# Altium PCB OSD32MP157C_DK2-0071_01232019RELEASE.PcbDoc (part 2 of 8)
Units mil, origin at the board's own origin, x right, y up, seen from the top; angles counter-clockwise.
Board outline 3976.38 x 2795.28 mil, 6 copper layers (Top Layer, Signal Layer 1, Signal Layer 2, Signal Layer 3, Signal Layer 4, Bottom Layer), stack 61.268 mil thick; 404 components, 418 nets, 1720 pads, 1233 vias.
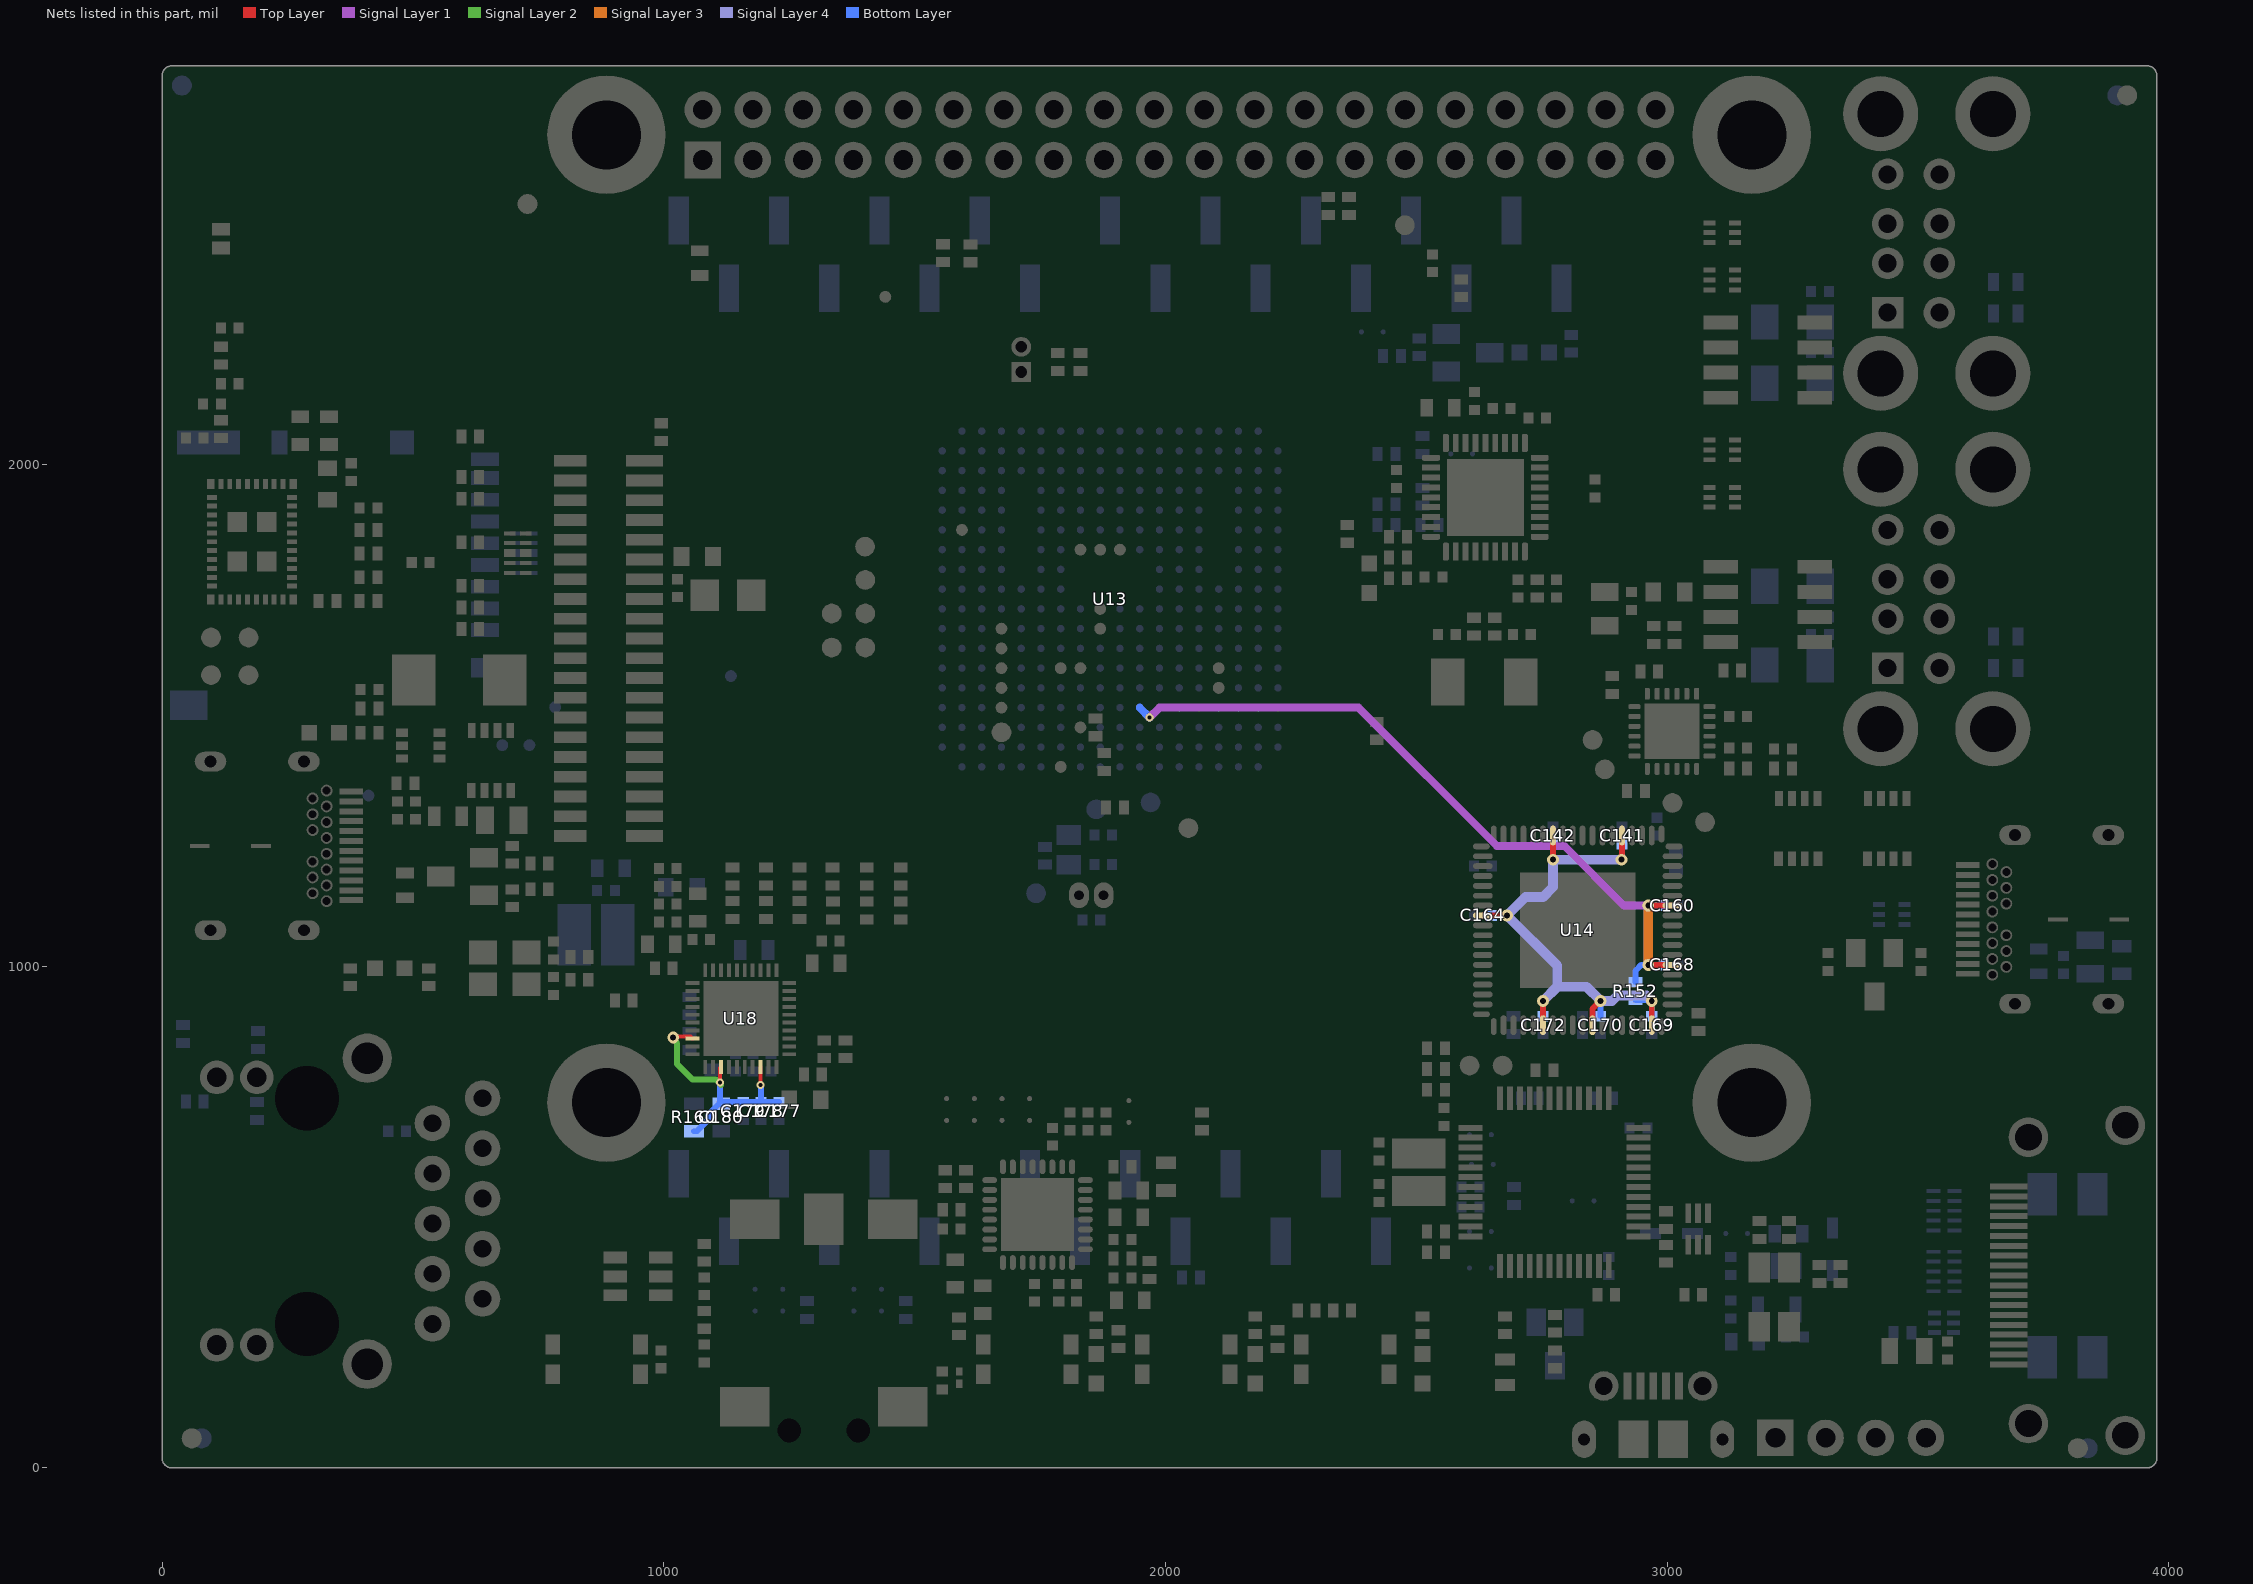
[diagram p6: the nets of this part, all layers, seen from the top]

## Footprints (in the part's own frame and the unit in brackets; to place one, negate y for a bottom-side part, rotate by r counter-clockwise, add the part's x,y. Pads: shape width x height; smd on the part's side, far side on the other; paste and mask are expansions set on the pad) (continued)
CON_HDMI_FCI-AMPHENOL_10029449-001RLF [mm]
  rect 0.3x1.9 smd mask+0.05: 1(4.75,8.5) 2(4.25,8.5) 3(3.75,8.5) 4(3.25,8.5) 5(2.75,8.5) 6(2.25,8.5) 7(1.75,8.5) 8(1.25,8.5) 9(0.75,8.5) 10(0.25,8.5) 11(-0.25,8.5) 12(-0.75,8.5) 13(-1.25,8.5) 14(-1.75,8.5) 15(-2.25,8.5) 16(-2.75,8.5) 17(-3.25,8.5) 18(-3.75,8.5) 19(-4.25,8.5)
  round 2 hole 1.35 mask+0.1: 20(7.25,7.5) 21(-7.25,7.5) 22(7.85,2.6) 23(-7.85,2.6)
  silkscreen extent -7.5,-1 7.5,8, body extent -8.1,-1 8.1,8.9, height 6.3
CON_JACK-3P5-SMT_LUMBERG_1503-13-VP3 [mm]
  rect 2.6x2 smd mask+0.05: 1(15.2,0)
  rect 2x2.5 smd mask+0.05: 2(15.2,3.5) 3(15.2,-3.5) 4(5.7,-4) 4(5.7,4)
  round 0.5 hole 1.2 unplated mask+0.1: NPTH1(4.5,-1.75) NPTH2(4.5,1.75)
  silkscreen extent 0,-3.55 14.6,3.55, body extent 0,-4.55 15.8,4.55, height 6.1
CON_MOLEX_53047-0210 [mm]
  oval 1x1.3 hole 0.5 mask+0.05: 1(-0.625,0) 2(0.625,0)
  silkscreen extent -2.12,-1.15 2.13,2.05, body extent -2.13,-1.15 2.13,2.05, height 4.2
CON_SAMTEC_SSW-106-22-X-S-VS [mil]
  rect 40x95 smd mask+1.97: 1(250,67.5) 2(150,-67.5) 3(50,67.5) 4(-50,-67.5) 5(-150,67.5) 6(-250,-67.5)
  silkscreen extent -310,-48 310,48, body extent -310,-101 310,102, height 385
CON_SAMTEC_SSW-108-22-X-S-VS [mil]
  rect 40x95 smd mask+1.97: 1(350,67.5) 2(250,-67.5) 3(150,67.5) 4(50,-67.5) 5(-50,67.5) 6(-150,-67.5) 7(-250,67.48) 8(-350,-67.48)
  silkscreen extent -410,-48 410,48, body extent -410,-101 410,102, height 385
CON_SAMTEC_SSW-110-22-X-S-VS [mil]
  rect 40x95 smd mask+1.97: 1(450,67.5) 2(350,-67.5) 3(250,67.5) 4(150,-67.5) 5(50,67.5) 6(-50,-67.5) 7(-150,67.48) 8(-250,-67.48) 9(-350,67.48) 10(-450,-67.48)
  silkscreen extent -510,-48 510,48, body extent -510,-101 510,102, height 385
CON_SAMTEC_TSW-104-07-G-S [mm]
  rect 1.85x1.85 / inner round 1.85 / far side rect 1.85x1.85 hole 1 mask+0.05: 1(-3.81,0)
  round 1.85 hole 1 mask+0.05: 2(-1.27,0) 3(1.27,0) 4(3.81,0)
  silkscreen extent -5.12,-1.3 5.12,1.3, body extent -5.21,-1.37 5.18,1.37, height 8.38
CON_SAMTEC_TSW-120-07-G-D [mm]
  rect 1.85x1.85 / inner round 1.85 / far side rect 1.85x1.85 hole 1 mask+0.05: 1(-24.13,-1.27)
  round 1.85 hole 1 mask+0.05: 2(-24.13,1.27) 3(-21.59,-1.27) 4(-21.59,1.27) 5(-19.05,-1.27) 6(-19.05,1.27) 7(-16.51,-1.27) 8(-16.51,1.27) 9(-13.97,-1.27) 10(-13.97,1.27) 11(-11.43,-1.27) 12(-11.43,1.27) 13(-8.89,-1.27) 14(-8.89,1.27) 15(-6.35,-1.27) 16(-6.35,1.27) 17(-3.81,-1.27) 18(-3.81,1.27) 19(-1.27,-1.27) 20(-1.27,1.27) 21(1.27,-1.27) 22(1.27,1.27) 23(3.81,-1.27) 24(3.81,1.27) 25(6.35,-1.27) 26(6.35,1.27) 27(8.89,-1.27) 28(8.89,1.27) 29(11.43,-1.27) 30(11.43,1.27) 31(13.97,-1.27) 32(13.97,1.27) 33(16.51,-1.27) 34(16.51,1.27) 35(19.05,-1.27) 36(19.05,1.27) 37(21.59,-1.27) 38(21.59,1.27) 39(24.13,-1.27) 40(24.13,1.27)
  silkscreen extent -25.4,-2.54 25.4,2.54, body extent -25.4,-2.55 25.4,2.54, height 8.38
CON_TE-CONNECTIVITY_2-1734248-0 [mm]
  rect 0.6x1.85 smd mask+0.05: 1(9.5,1.925) 3(8.5,1.925) 5(7.5,1.925) 7(6.5,1.925) 9(5.5,1.925) 11(4.5,1.925) 13(3.5,1.925) 15(2.5,1.925) 17(1.5,1.925) 19(0.5,1.925) 21(-0.5,1.925) 23(-1.5,1.925) 25(-2.5,1.925) 27(-3.5,1.925) 29(-4.5,1.925) 31(-5.5,1.925) 33(-6.5,1.925) 35(-7.5,1.925) 37(-8.5,1.925) 39(-9.5,1.925)
  rect 0.6x1.65 smd mask+0.05: 2(9.5,-1.825) 4(8.5,-1.825) 6(7.5,-1.825) 8(6.5,-1.825) 10(5.5,-1.825) 12(4.5,-1.825) 14(3.5,-1.825) 16(2.5,-1.825) 18(1.5,-1.825) 20(0.5,-1.825) 22(-0.5,-1.825) 24(-1.5,-1.825) 26(-2.5,-1.825) 28(-3.5,-1.825) 30(-4.5,-1.825) 32(-5.5,-1.825) 34(-6.5,-1.825) 36(-7.5,-1.825) 38(-8.5,-1.825) 40(-9.5,-1.825)
  silkscreen extent -13.7,-2.8 13.7,1.9, body extent -13.7,-2.65 13.7,2.4, height 7.7
CON_USB-TYPEC_COXOC_317JD24BZTF3K3C3 [mm]
  rect 0.2x1 smd paste-10 mask+0: 0(0,6) 0(0,2.9)
  rect 0.3x1.2 smd mask+0.05: A1(-2.75,10.58) A2(-2.25,10.58) A3(-1.75,10.58) A4(-1.25,10.58) A5(-0.75,10.58) A6(-0.25,10.58) A7(0.25,10.58) A8(0.75,10.58) A9(1.25,10.58) A10(1.75,10.58) A11(2.25,10.58) A12(2.75,10.58)
  round 0.6 hole 0.4 mask+0.05: B1(2,9.33) B1(2.8,9.33) B2(2.4,8.62) B3(1.6,8.62) B4(1.2,9.33) B5(0.8,8.62) B6(0.4,9.33) B7(-0.4,9.33) B8(-0.8,8.62) B9(-1.2,9.33) B10(-1.6,8.62) B11(-2.4,8.62) B12(-2.8,9.33) B12(-2,9.33)
  oval 1x1.6 hole 0.6 slot 1.2 at 90 deg mask+0.05: SH1(-4.27,8.18) SH2(-4.27,3.45) SH3(4.27,8.18) SH4(4.27,3.45)
  silkscreen extent -4.38,-0.95 4.38,10.38, body extent -4.38,-0.95 4.38,10.84, height 3.03
CON_USBMICROB_MOLEX_105017-0001_H2P90 [mm]
  rect 0.4x1.35 smd mask+0.05: 1(-1.3,4.15) 2(-0.65,4.15) 3(0,4.15) 4(0.65,4.15) 5(1.3,4.15)
  round 1.5 hole 0.9 mask+0.05: 6(-2.5,4.15) 7(2.5,4.15)
  oval 1.2x1.9 hole 0.6 slot 1.3 at 90 deg mask+0.05: 8(3.5,1.45) 9(-3.5,1.45)
  rect 1.5x1.9 smd mask+0.05: 10(-1,1.45) 11(1,1.45)
  Top Layer region: 2.3,2.4 3.5,2.4 3.5,0.5 2.3,0.5 2.3,2.4
  Top Layer region: -3.5,2.4 -2.3,2.4 -2.3,0.5 -3.5,0.5 -3.5,2.4
  silkscreen extent -4,-0.7 4,4.6, body extent -4.1,-1.15 4.1,4.66, height 2.9
CPOL_TAJ-A_1206_H180 [mm]
  rect 1.45x1.6 smd mask+0.05: 1(-1.175,0) 2(1.175,0)
  silkscreen extent -2.15,-1.05 1.7,1.05, body extent -1.7,-0.9 1.7,0.9, height 1.8
CPOL_TAJ-C_2312_H2P6 [mm]
  rect 2.2x2.6 smd mask+0.05: 1(-2.3,0) 2(2.3,0)
  silkscreen extent -3.6,-1.85 3.1,1.85, body extent -3.1,-1.7 3.1,1.7, height 2.8
CRY_NX2012SA_2P [mm]
  rect 1x1.25 smd mask+0.05: 1(-0.75,0) 2(0.75,0)
  silkscreen extent -1.05,-0.75 1.05,0.75, body extent -1.05,-0.63 1.05,0.63, height 0.6
CRY_NX3225GD_2P [mm]
  rect 1.5x2.7 smd mask+0.05: 1(-0.95,0) 2(0.95,0)
  silkscreen extent -0.1,-1.3 0.1,1.3, body extent -1.65,-1.3 1.65,1.3, height 1
CRY_NX3225HA_4P [mm]
  rect 1.4x1.2 smd mask+0.05: 1(-1.1,-0.8) 2(1.1,-0.8) 3(1.1,0.8) 4(-1.1,0.8)
  silkscreen extent -1.9,-1.5 1.65,1.3, body extent -1.66,-1.31 1.66,1.31, height 0.91
CRY_TXC_7A-SERIES_5X3P2_H1P2_2P [mm]
  rect 1.7x2.4 smd mask+0.05: 1(-1.85,0) 2(1.85,0)
  silkscreen extent -2.6,-1.7 2.6,1.7, body extent -2.6,-1.7 2.6,1.7, height 1.35
DIO_SOD323 [mm]
  rect 1.06x0.54 smd mask+0.05: 1(-1.07,0) 2(1.07,0)
  silkscreen extent -0.9,-0.72 0.9,0.72, body extent -1.3,-0.78 1.3,0.78, height 1.17
DIO_SOT363 [mm]
  rect 0.42x0.6 smd mask+0.05: 1(-0.65,-0.95) 2(0,-0.95) 3(0.65,-0.95) 4(0.65,0.95) 5(0,0.95) 6(-0.65,0.95)
  silkscreen extent -1.1,-0.67 1.1,0.67, body extent -1.1,-1.2 1.1,1.2, height 1.1
DM3BT-DSF-PEJS [mm] "Micro SD conn SMT bottom mount push-push"
  rect 0.7x1.4 smd: 1(-2.85,7.5) 2(-1.75,7.5) 3(-0.65,7.5) 4(0.45,7.5) 5(1.55,7.5) 6(2.65,7.5) 7(3.75,7.5) 8(4.85,7.5) 9(5.8,7.5)
  rect 1.2x1.2 smd: 10(6.65,3.3)
  rect 1.2x0.8 smd: 11(6.65,-2.9)
  rect 1.2x3.2 smd: 12(6.65,-6.5)
  rect 1.5x1.9 smd: 13(-6.65,-7.5)
  rect 1x1.4 smd: 14(-4.75,7.5)
  Top Layer keep-out region: 6.4,7.15 7.15,7.15 7.15,3.91 6.4,3.91
  Top Layer keep-out region: 6.4,2.7 7.15,2.7 7.15,-0.9 6.4,-0.9
  silkscreen extent -7.15,-8.3 6.95,8, body extent -7.01,-9.89 6.84,7.66, height 1.85
ESD_QFN1610_2N_1K_2A [mm] "DFN, 2-Leads, Body 1.60x1.00mm"
  rect 0.55x0.9 smd mask+0.05: 1(-0.625,0) 2(0.625,0)
  silkscreen extent -1.02,-0.58 0.85,0.58, body extent -0.85,-0.55 0.85,0.55, height 0.6
ESD_QFN-6L_1P7X1P5_P050 [mm]
  rect 0.25x0.6 smd mask+0.05: 1(-0.5,-0.65) 2(0,-0.65) 3(0.5,-0.65) 4(0.5,0.65) 5(0,0.65) 6(-0.5,0.65)
  silkscreen extent -0.9,-0.8 0.9,0.8, body extent -0.9,-0.8 0.9,0.8, height 0.56
ESD_SOT23 [mm]
  rect 1x1.4 smd mask+0.05: 1(-0.95,-1.1) 2(0.95,-1.1) 3(0,1.1)
  silkscreen extent -1.63,-0.82 1.63,0.82, body extent -1.56,-1.5 1.56,1.5, height 1.4
ESD_SOT23-6L [mm]
  rect 0.6x1.2 smd mask+0.05: 1(-0.95,-1.15) 2(0,-1.15) 3(0.95,-1.15) 4(0.95,1.15) 5(0,1.15) 6(-0.95,1.15)
  silkscreen extent -1.53,-0.87 1.53,0.87, body extent -1.52,-1.5 1.52,1.5, height 1.45
ESD_SOT666 [mm]
  rect 0.3x0.99 smd mask+0.05: 1(-0.5,-0.805) 2(0,-0.805) 3(0.5,-0.805) 4(0.5,0.805) 5(0,0.805) 6(-0.5,0.805)
  silkscreen extent -0.85,-0.65 0.85,0.65, body extent -0.85,-0.8 0.85,0.8, height 0.6
ESD_ST0201 [mm]
  rect 0.425x0.33 smd mask+0.05: 1(-0.312,0) 2(0.312,0)
  silkscreen extent -0.55,-0.3 0.33,0.3, body extent -0.34,-0.18 0.34,0.18, height 0.34
ESD_UQFN-6L_1P45X1_P050 [mm]
  rect 0.25x0.65 smd mask+0.05: 1(-0.5,-0.475) 2(0,-0.475) 3(0.5,-0.475) 4(0.5,0.475) 5(0,0.475) 6(-0.5,0.475)
  silkscreen extent -0.9,-0.87 0.77,0.55, body extent -0.77,-0.55 0.77,0.55, height 0.66
ESD_UQFN-10L_2P5X1_P050 [mm]
  rect 0.2x0.58 smd mask+0.05: 1(-1,-0.41) 2(-0.5,-0.41) 4(0.5,-0.41) 5(1,-0.41) 6(1,0.41) 7(0.5,0.41) 9(-0.5,0.41) 10(-1,0.41)
  rect 0.4x0.58 smd mask+0.05: 3(0,-0.41) 8(0,0.41)
  silkscreen extent -1.38,-0.63 1.38,0.63, body extent -1.3,-0.55 1.3,0.55, height 0.51
ESD_UQFN-10L_2P60X1P35_P050 [mm]
  rect 0.2x0.7 smd mask+0.05: 1(-1,-0.525) 2(-0.5,-0.525) 3(0,-0.525) 4(0.5,-0.525) 5(1,-0.525) 6(1,0.525) 7(0.5,0.525) 8(0,0.525) 9(-0.5,0.525) 10(-1,0.525)
  silkscreen extent -1.45,-0.95 1.33,0.7, body extent -1.33,-0.7 1.33,0.7, height 0.56
FIL_0603_H0P65 [mm]
  rect 0.8x0.95 smd mask+0.05: 1(-0.8,0) 2(0.8,0)
  silkscreen extent -1.33,-0.6 1.33,0.6, body extent -0.87,-0.47 0.87,0.47, height 0.65
ICC_BGA324_18X18_OSD32MP157CAC3 [mm] "ICC_BGA324_18X18_OSD32MP157CAC3"
  round 0.375 smd paste+0 mask+0.05: A2(-7.5,8.5) A3(-6.5,8.5) A4(-5.5,8.5) A5(-4.5,8.5) A6(-3.5,8.5) A7(-2.5,8.5) A8(-1.5,8.5) A9(-0.5,8.5) A10(0.5,8.5) A11(1.5,8.5) A12(2.5,8.5) A13(3.5,8.5) A14(4.5,8.5) A15(5.5,8.5) A16(6.5,8.5) A17(7.5,8.5) B1(-8.5,7.5) B2(-7.5,7.5) B3(-6.5,7.5) B4(-5.5,7.5) B5(-4.5,7.5) B6(-3.5,7.5) B7(-2.5,7.5) B8(-1.5,7.5) B9(-0.5,7.5) B10(0.5,7.5) B11(1.5,7.5) B12(2.5,7.5) B13(3.5,7.5) B14(4.5,7.5) B15(5.5,7.5) B16(6.5,7.5) B17(7.5,7.5) B18(8.5,7.5) C1(-8.5,6.5) C2(-7.5,6.5) C3(-6.5,6.5) C4(-5.5,6.5) C5(-4.5,6.5) C6(-3.5,6.5) C7(-2.5,6.5) C8(-1.5,6.5) C9(-0.5,6.5) C10(0.5,6.5) C11(1.5,6.5) C12(2.5,6.5) C13(3.5,6.5) C14(4.5,6.5) C15(5.5,6.5) C16(6.5,6.5) C17(7.5,6.5) C18(8.5,6.5) D1(-8.5,5.5) D2(-7.5,5.5) D3(-6.5,5.5) D4(-5.5,5.5) D5(-4.5,5.5) D6(-3.5,5.5) D7(-2.5,5.5) D8(-1.5,5.5) D9(-0.5,5.5) D10(0.5,5.5) D16(6.5,5.5) D17(7.5,5.5) D18(8.5,5.5) E1(-8.5,4.5) E2(-7.5,4.5) E3(-6.5,4.5) E4(-5.5,4.5) E5(-4.5,4.5) E6(-3.5,4.5) E7(-2.5,4.5) E8(-1.5,4.5) E9(-0.5,4.5) E10(0.5,4.5) E11(1.5,4.5) E12(2.5,4.5) E13(3.5,4.5) E14(4.5,4.5) E15(5.5,4.5) E16(6.5,4.5) E17(7.5,4.5) E18(8.5,4.5) F1(-8.5,3.5) F2(-7.5,3.5) F3(-6.5,3.5) F4(-5.5,3.5) F5(-4.5,3.5) F6(-3.5,3.5) F7(-2.5,3.5) F8(-1.5,3.5) F9(-0.5,3.5) F10(0.5,3.5) F11(1.5,3.5) F12(2.5,3.5) F13(3.5,3.5) F14(4.5,3.5) F15(5.5,3.5) F16(6.5,3.5) F17(7.5,3.5) F18(8.5,3.5) G1(-8.5,2.5) G2(-7.5,2.5) G3(-6.5,2.5) G4(-5.5,2.5) G5(-4.5,2.5) G6(-3.5,2.5) G7(-2.5,2.5) G8(-1.5,2.5) G9(-0.5,2.5) G10(0.5,2.5) G11(1.5,2.5) G12(2.5,2.5) G13(3.5,2.5) G14(4.5,2.5) G15(5.5,2.5) G16(6.5,2.5) G17(7.5,2.5) G18(8.5,2.5) H1(-8.5,1.5) H2(-7.5,1.5) H3(-6.5,1.5) H4(-5.5,1.5) H5(-4.5,1.5) H6(-3.5,1.5) H7(-2.5,1.5) H8(-1.5,1.5) H9(-0.5,1.5) H12(2.5,1.5) H13(3.5,1.5) H14(4.5,1.5) H15(5.5,1.5) H16(6.5,1.5) H17(7.5,1.5) H18(8.5,1.5) J1(-8.5,0.5) J2(-7.5,0.5) J3(-6.5,0.5) J4(-5.5,0.5) J5(-4.5,0.5) J6(-3.5,0.5) J7(-2.5,0.5) J8(-1.5,0.5) J9(-0.5,0.5) J12(2.5,0.5) J13(3.5,0.5) J14(4.5,0.5) J15(5.5,0.5) J16(6.5,0.5) J17(7.5,0.5) J18(8.5,0.5) K1(-8.5,-0.5) K2(-7.5,-0.5) K3(-6.5,-0.5) K4(-5.5,-0.5) K5(-4.5,-0.5) K6(-3.5,-0.5) K7(-2.5,-0.5) K8(-1.5,-0.5) K9(-0.5,-0.5) K12(2.5,-0.5) K13(3.5,-0.5) K14(4.5,-0.5) K15(5.5,-0.5) K16(6.5,-0.5) K17(7.5,-0.5) K18(8.5,-0.5) L1(-8.5,-1.5) L2(-7.5,-1.5) L3(-6.5,-1.5) L4(-5.5,-1.5) L5(-4.5,-1.5) L6(-3.5,-1.5) L7(-2.5,-1.5) L8(-1.5,-1.5) L9(-0.5,-1.5) L12(2.5,-1.5) L13(3.5,-1.5) L14(4.5,-1.5) L15(5.5,-1.5) L16(6.5,-1.5) L17(7.5,-1.5) L18(8.5,-1.5) M1(-8.5,-2.5) M2(-7.5,-2.5) M3(-6.5,-2.5) M4(-5.5,-2.5) M5(-4.5,-2.5) M6(-3.5,-2.5) M7(-2.5,-2.5) M8(-1.5,-2.5) M9(-0.5,-2.5) M10(0.5,-2.5) M11(1.5,-2.5) M12(2.5,-2.5) M13(3.5,-2.5) M14(4.5,-2.5) M15(5.5,-2.5) M16(6.5,-2.5) M17(7.5,-2.5) M18(8.5,-2.5) N1(-8.5,-3.5) N2(-7.5,-3.5) N3(-6.5,-3.5) N4(-5.5,-3.5) N5(-4.5,-3.5) N6(-3.5,-3.5) N7(-2.5,-3.5) N8(-1.5,-3.5) N9(-0.5,-3.5) N10(0.5,-3.5) N11(1.5,-3.5) N12(2.5,-3.5) N13(3.5,-3.5) N14(4.5,-3.5) N15(5.5,-3.5) N16(6.5,-3.5) N17(7.5,-3.5) N18(8.5,-3.5) P1(-8.5,-4.5) P2(-7.5,-4.5) P3(-6.5,-4.5) P4(-5.5,-4.5) P5(-4.5,-4.5) P6(-3.5,-4.5) P7(-2.5,-4.5) P8(-1.5,-4.5) P9(-0.5,-4.5) P10(0.5,-4.5) P16(6.5,-4.5) P17(7.5,-4.5) P18(8.5,-4.5) R1(-8.5,-5.5) R2(-7.5,-5.5) R3(-6.5,-5.5) R4(-5.5,-5.5) R5(-4.5,-5.5) R6(-3.5,-5.5) R7(-2.5,-5.5) R8(-1.5,-5.5) R9(-0.5,-5.5) R10(0.5,-5.5) R11(1.5,-5.5) R12(2.5,-5.5) R13(3.5,-5.5) R14(4.5,-5.5) R15(5.5,-5.5) R16(6.5,-5.5) R17(7.5,-5.5) R18(8.5,-5.5) T1(-8.5,-6.5) T2(-7.5,-6.5) T3(-6.5,-6.5) T4(-5.5,-6.5) T5(-4.5,-6.5) T6(-3.5,-6.5) T7(-2.5,-6.5) T8(-1.5,-6.5) T9(-0.5,-6.5) T10(0.5,-6.5) T11(1.5,-6.5) T12(2.5,-6.5) T13(3.5,-6.5) T14(4.5,-6.5) T15(5.5,-6.5) T16(6.5,-6.5) T17(7.5,-6.5) T18(8.5,-6.5) U1(-8.5,-7.5) U2(-7.5,-7.5) U3(-6.5,-7.5) U4(-5.5,-7.5) U5(-4.5,-7.5) U6(-3.5,-7.5) U7(-2.5,-7.5) U8(-1.5,-7.5) U9(-0.5,-7.5) U10(0.5,-7.5) U11(1.5,-7.5) U12(2.5,-7.5) U13(3.5,-7.5) U14(4.5,-7.5) U15(5.5,-7.5) U16(6.5,-7.5) U17(7.5,-7.5) U18(8.5,-7.5) V2(-7.5,-8.5) V3(-6.5,-8.5) V4(-5.5,-8.5) V5(-4.5,-8.5) V6(-3.5,-8.5) V7(-2.5,-8.5) V8(-1.5,-8.5) V9(-0.5,-8.5) V10(0.5,-8.5) V11(1.5,-8.5) V12(2.5,-8.5) V13(3.5,-8.5) V14(4.5,-8.5) V15(5.5,-8.5) V16(6.5,-8.5) V17(7.5,-8.5)
  silkscreen extent -9.27,-9 9,9.28, body extent -9.5,-9.5 9.5,9.5, height 1.75
ICC_LQFP48_7X7_P050 [mm]
  rect 0.3x1.2 smd mask+0.05: 1(-2.75,-4.25) 2(-2.25,-4.25) 3(-1.75,-4.25) 4(-1.25,-4.25) 5(-0.75,-4.25) 6(-0.25,-4.25) 7(0.25,-4.25) 8(0.75,-4.25) 9(1.25,-4.25) 10(1.75,-4.25) 11(2.25,-4.25) 12(2.75,-4.25) 25(2.75,4.25) 26(2.25,4.25) 27(1.75,4.25) 28(1.25,4.25) 29(0.75,4.25) 30(0.25,4.25) 31(-0.25,4.25) 32(-0.75,4.25) 33(-1.25,4.25) 34(-1.75,4.25) 35(-2.25,4.25) 36(-2.75,4.25)
  rect 1.2x0.3 smd mask+0.05: 13(4.25,-2.75) 14(4.25,-2.25) 15(4.25,-1.75) 16(4.25,-1.25) 17(4.25,-0.75) 18(4.25,-0.25) 19(4.25,0.25) 20(4.25,0.75) 21(4.25,1.25) 22(4.25,1.75) 23(4.25,2.25) 24(4.25,2.75) 37(-4.25,2.75) 38(-4.25,2.25) 39(-4.25,1.75) 40(-4.25,1.25) 41(-4.25,0.75) 42(-4.25,0.25) 43(-4.25,-0.25) 44(-4.25,-0.75) 45(-4.25,-1.25) 46(-4.25,-1.75) 47(-4.25,-2.25) 48(-4.25,-2.75)
  silkscreen extent -3.52,-3.52 3.52,3.52, body extent -4.5,-4.5 4.5,4.5, height 1.6
ICC_QFN24-EPAD_4X4_P050 [mm]
  rrect50% 0.6x0.25 smd mask+0.05: 1(-1.9,1.25) 2(-1.9,0.75) 3(-1.9,0.25) 4(-1.9,-0.25) 5(-1.9,-0.75) 6(-1.9,-1.25) 13(1.9,-1.25) 14(1.9,-0.75) 15(1.9,-0.25) 16(1.9,0.25) 17(1.9,0.75) 18(1.9,1.25)
  rrect50% 0.25x0.6 smd mask+0.05: 7(-1.25,-1.9) 8(-0.75,-1.9) 9(-0.25,-1.9) 10(0.25,-1.9) 11(0.75,-1.9) 12(1.25,-1.9) 19(1.25,1.9) 20(0.75,1.9) 21(0.25,1.9) 22(-0.25,1.9) 23(-0.75,1.9) 24(-1.25,1.9)
  rect 2.8x2.8 smd paste-10 mask+0.05: ep(0,0)
  silkscreen extent -2,-2 2,2, body extent -2.05,-2.05 2.05,2.05, height 1.1
ICC_QFN32-EPAD_5X5_P050 [mm]
  oval 0.3x0.75 smd mask+0.05: 1(-1.75,-2.425) 2(-1.25,-2.425) 3(-0.75,-2.425) 4(-0.25,-2.425) 5(0.25,-2.425) 6(0.75,-2.425) 7(1.25,-2.425) 8(1.75,-2.425) 17(1.75,2.425) 18(1.25,2.425) 19(0.75,2.425) 20(0.25,2.425) 21(-0.25,2.425) 22(-0.75,2.425) 23(-1.25,2.425) 24(-1.75,2.425)
  oval 0.75x0.3 smd mask+0.05: 9(2.425,-1.75) 10(2.425,-1.25) 11(2.425,-0.75) 12(2.425,-0.25) 13(2.425,0.25) 14(2.425,0.75) 15(2.425,1.25) 16(2.425,1.75) 25(-2.425,1.75) 26(-2.425,1.25) 27(-2.425,0.75) 28(-2.425,0.25) 29(-2.425,-0.25) 30(-2.425,-0.75) 31(-2.425,-1.25) 32(-2.425,-1.75)
  rect 3.7x3.7 smd mask+0.05: 33(0,0)
  silkscreen extent -2.63,-2.63 2.63,2.63, body extent -2.55,-2.55 2.55,2.55, height 1
ICC_QFN36-EPAD_6X6_P050 [mm]
  rrect50% 0.3x0.9 smd mask+0.05: 1(-2,-2.75) 9(2,-2.75) 19(2,2.75) 27(-2,2.75)
  rect 0.3x0.9 smd mask+0.05: 2(-1.5,-2.75) 3(-1,-2.75) 4(-0.5,-2.75) 5(0,-2.75) 6(0.5,-2.75) 7(1,-2.75) 8(1.5,-2.75) 20(1.5,2.75) 21(1,2.75) 22(0.5,2.75) 23(0,2.75) 24(-0.5,2.75) 25(-1,2.75) 26(-1.5,2.75)
  rrect50% 0.9x0.3 smd mask+0.05: 10(2.75,-2) 18(2.75,2) 28(-2.75,2) 36(-2.75,-2)
  rect 0.9x0.3 smd mask+0.05: 11(2.75,-1.5) 12(2.75,-1) 13(2.75,-0.5) 14(2.75,0) 15(2.75,0.5) 16(2.75,1) 17(2.75,1.5) 29(-2.75,1.5) 30(-2.75,1) 31(-2.75,0.5) 32(-2.75,0) 33(-2.75,-0.5) 34(-2.75,-1) 35(-2.75,-1.5)
  rect 3.9x3.9 smd mask+0.05: 37(0,0)
  silkscreen extent -3.15,-3.15 3.15,3.15, body extent -3.06,-3.06 3.06,3.06, height 1
ICC_QFN40-EPAD_5X5_P040 [mm]
  rect 0.7x0.2 smd mask+0.05: 1(-2.45,1.8) 2(-2.45,1.4) 3(-2.45,1) 4(-2.45,0.6) 5(-2.45,0.2) 6(-2.45,-0.2) 7(-2.45,-0.6) 8(-2.45,-1) 9(-2.45,-1.4) 10(-2.45,-1.8) 21(2.45,-1.8) 22(2.45,-1.4) 23(2.45,-1) 24(2.45,-0.6) 25(2.45,-0.2) 26(2.45,0.2) 27(2.45,0.6) 28(2.45,1) 29(2.45,1.4) 30(2.45,1.8)
  rect 0.2x0.7 smd mask+0.05: 11(-1.8,-2.45) 12(-1.4,-2.45) 13(-1,-2.45) 14(-0.6,-2.45) 15(-0.2,-2.45) 16(0.2,-2.45) 17(0.6,-2.45) 18(1,-2.45) 19(1.4,-2.45) 20(1.8,-2.45) 31(1.8,2.45) 32(1.4,2.45) 33(1,2.45) 34(0.6,2.45) 35(0.2,2.45) 36(-0.2,2.45) 37(-0.6,2.45) 38(-1,2.45) 39(-1.4,2.45) 40(-1.8,2.45)
  rect 3.8x3.8 smd mask+0.05: 41(0,0)
  silkscreen extent -2.5,-2.5 2.5,2.5, body extent -2.5,-2.5 2.5,2.5, height 0.91
ICC_QFN72-EPAD_10X10_P050 [mm]
  oval 0.85x0.3 smd mask+0.05: 1(-4.875,4.25) 18(-4.875,-4.25) 37(4.875,-4.25) 54(4.875,4.25)
  oval 1x0.3 smd mask+0.05: 2(-4.8,3.75) 3(-4.8,3.25) 4(-4.8,2.75) 5(-4.8,2.25) 6(-4.8,1.75) 7(-4.8,1.25) 8(-4.8,0.75) 9(-4.8,0.25) 10(-4.8,-0.25) 11(-4.8,-0.75) 12(-4.8,-1.25) 13(-4.8,-1.75) 14(-4.8,-2.25) 15(-4.8,-2.75) 16(-4.8,-3.25) 17(-4.8,-3.75) 38(4.8,-3.75) 39(4.8,-3.25) 40(4.8,-2.75) 41(4.8,-2.25) 42(4.8,-1.75) 43(4.8,-1.25) 44(4.8,-0.75) 45(4.8,-0.25) 46(4.8,0.25) 47(4.8,0.75) 48(4.8,1.25) 49(4.8,1.75) 50(4.8,2.25) 51(4.8,2.75) 52(4.8,3.25) 53(4.8,3.75)
  oval 0.3x0.85 smd mask+0.05: 19(-4.25,-4.875) 36(4.25,-4.875) 55(4.25,4.875) 72(-4.25,4.875)
  oval 0.3x1 smd mask+0.05: 20(-3.75,-4.8) 21(-3.25,-4.8) 22(-2.75,-4.8) 23(-2.25,-4.8) 24(-1.75,-4.8) 25(-1.25,-4.8) 26(-0.75,-4.8) 27(-0.25,-4.8) 28(0.25,-4.8) 29(0.75,-4.8) 30(1.25,-4.8) 31(1.75,-4.8) 32(2.25,-4.8) 33(2.75,-4.8) 34(3.25,-4.8) 35(3.75,-4.8) 56(3.75,4.8) 57(3.25,4.8) 58(2.75,4.8) 59(2.25,4.8) 60(1.75,4.8) 61(1.25,4.8) 62(0.75,4.8) 63(0.25,4.8) 64(-0.25,4.8) 65(-0.75,4.8) 66(-1.25,4.8) 67(-1.75,4.8) 68(-2.25,4.8) 69(-2.75,4.8) 70(-3.25,4.8) 71(-3.75,4.8)
  rect 5.85x5.85 smd mask+0.05: e-Pad(0,0)
  silkscreen extent -4.9,-4.9 4.9,4.9, body extent -5,-5 5,5, height 0.91
ICC_SO8_5X4_P127 [mm]
  rect 0.7x1.75 smd mask+0.05: 1(-1.905,-2.375) 2(-0.635,-2.375) 3(0.635,-2.375) 4(1.905,-2.375) 5(1.905,2.375) 6(0.635,2.375) 7(-0.635,2.375) 8(-1.905,2.375)
  silkscreen extent -2.58,-2 2.58,2, body extent -2.57,-3 2.57,3, height 1.75
IND_0402_MURATA_LQW15AN2N4C00X [mm]
  rect 0.65x0.9 smd mask+0.05: 1(-0.475,0) 2(0.475,0)
  silkscreen extent -0.05,-0.35 0.05,0.35, body extent -0.55,-0.35 0.55,0.35, height 0.6
L0603 [mm]
  rect 0.8x0.95 smd mask+0.05: 1(-0.8,0) 2(0.8,0)
  silkscreen extent -1.33,-0.6 1.33,0.6, body extent -0.87,-0.47 0.87,0.47, height 0.95
L1210_LQH [mm]
  rect 1.7x3.1 smd mask+0.05: 1(-1.1,0) 2(1.1,0)
  silkscreen extent -2.05,-1.65 2.05,1.65, body extent -1.75,-1.35 1.75,1.35, height 2
LED_0603_GREEN [mm]
  rect 0.8x0.8 smd mask+0.05: 1(-0.75,0) 2(0.75,0)
  silkscreen extent -0.25,-0.4 1.25,0.4, body extent -0.8,-0.4 0.8,0.4, height 0.6
LED_0603_ORANGE_H0P4 [mm]
  rect 0.8x0.8 smd mask+0.05: 1(-0.75,0) 2(0.75,0)
  silkscreen extent -0.25,-0.4 1.25,0.4, body extent -0.8,-0.4 0.79,0.4, height 0.4
LED_0603_RED [mm]
  rect 0.8x0.8 smd mask+0.05: 1(-0.75,0) 2(0.75,0)
  silkscreen extent -0.25,-0.4 1.25,0.4, body extent -0.8,-0.4 0.8,0.4, height 0.6
LED_0603_SMD-B_BLUE_H0P4 [mm]
  rect 0.6x1 smd mask+0.05: 1(-0.65,0) 2(0.65,0)
  silkscreen extent -0.23,-0.45 1.07,0.45, body extent -0.85,-0.45 0.85,0.45, height 0.5
LED_BI-GR_HSMF-A201-A00J1 [mm]
  rect 1.1x1.5 smd mask+0.05: 1(-0.75,-1.5) 2(-0.75,1.5) 3(0.75,1.5) 4(0.75,-1.5)
  silkscreen extent -1.65,-1.85 1.65,1.85, body extent -1.5,-1.85 1.5,1.85, height 2.1
MHDR1X2 [mm] "Connector; Header; 2 Position"
  rect 1x1 hole 0.6: 1(0,0)
  round 1 hole 0.6: 2(1.27,0)
  silkscreen extent -0.9,-0.9 2.17,0.9, body extent -0.63,-1.2 1.91,1.2, height 5
MOD_WLAN-BT_MURATA_LBEE5KL1DX-883 [mm]
  rect 0.25x0.5 smd mask+0.05: 1(-2.25,-2.025) 2(-1.8,-2.025) 3(-1.35,-2.025) 4(-0.9,-2.025) 5(-0.45,-2.025) 6(0,-2.025) 7(0.45,-2.025) 8(0.9,-2.025) 9(1.35,-2.025) 10(1.8,-2.025) 11(2.25,-2.025) 22(2.25,2.025) 23(1.8,2.025) 24(1.35,2.025) 25(0.9,2.025) 26(0.45,2.025) 27(0,2.025) 28(-0.45,2.025) 29(-0.9,2.025) 30(-1.35,2.025) 31(-1.8,2.025) 32(-2.25,2.025)
  rect 0.5x0.375 smd mask+0.05: 12(2.925,-2.087) 21(2.925,2.087) 33(-2.925,2.087) 42(-2.925,-2.087)
  rect 0.5x0.25 smd mask+0.05: 13(2.925,-1.575) 14(2.925,-1.125) 15(2.925,-0.675) 16(2.925,-0.225) 17(2.925,0.225) 18(2.925,0.675) 19(2.925,1.125) 20(2.925,1.575) 34(-2.925,1.575) 35(-2.925,1.125) 36(-2.925,0.675) 37(-2.925,0.225) 38(-2.925,-0.225) 39(-2.925,-0.675) 40(-2.925,-1.125) 41(-2.925,-1.575)
  rect 1x1 smd mask+0.05: 43(-1,-0.75) 44(1,-0.75) 45(-1,0.75) 46(1,0.75)
  silkscreen extent -3.57,-2.68 3.57,2.68, body extent -3.57,-2.68 3.57,2.68, height 1.11
MOS_POWERFLAT_3P3X3P3_P065 [mm]
  rect 0.4x0.75 smd mask+0.05: 1(-0.975,-1.525) 2(-0.325,-1.525) 3(0.325,-1.525) 4(0.975,-1.525) 6(0.325,1.525) 7(-0.325,1.525)
  rect 0.45x0.75 smd mask+0.05: 5(1,1.525) 8(-1,1.525)
  Top Layer region: -1.755,0.2 -1.755,-0.2 -1.225,-0.2 -1.225,-0.5 1.225,-0.5 1.225,-0.2 1.755,-0.2 1.755,0.2 1.225,0.2 1.225,1.9 -1.225,1.9 -1.225,0.2
  silkscreen extent -1.63,-1.55 1.63,1.55, body extent -1.75,-1.75 1.75,1.75, height 0.91
NPN_SOT23 [mm]
  rect 1x1.4 smd mask+0.05: 1(-0.95,-1.1) 2(0.95,-1.1) 3(0,1.1)
  silkscreen extent -1.63,-0.82 1.63,0.82, body extent -1.56,-1.25 1.56,1.25, height 1.1
PTH_M1261-3005-N_3P5X6_M3_H14 [mm]
  round 6 hole 3.5 mask+0.05: 1(0,0)
  silkscreen extent -3.25,-3.25 3.25,3.25, body extent -2.5,-2.5 2.5,2.5, height 14
R0402 [mm]
  rect 0.51x0.7 smd mask+0.05: 1(-0.45,0) 2(0.45,0)
  silkscreen extent -0.72,-0.43 0.72,0.43, body extent -0.52,-0.3 0.52,0.3, height 0.4
R0603 [mm]
  rect 0.64x1 smd mask+0.05: 1(-0.7,0) 2(0.7,0)
  silkscreen extent -1.05,-0.58 1.05,0.58, body extent -0.9,-0.5 0.9,0.5, height 0.56
R0805 [mm]
  rect 0.85x1.3 smd mask+0.05: 1(-0.875,0) 2(0.875,0)
  silkscreen extent -0.33,-0.67 0.33,0.67, body extent -1.05,-0.68 1.05,0.68, height 0.65
REG_SOT23-5L [mm]
  rect 0.6x1.3 smd mask+0.05: 1(-0.95,-1.1) 2(0,-1.1) 3(0.95,-1.1) 4(0.95,1.1) 5(-0.95,1.1)
  silkscreen extent -1.6,-0.95 1.6,0.97, body extent -1.52,-1.25 1.52,1.25, height 1.1
RJMG20162141BER [mm] "CONN MAGJACK 1PORT 1000 BASE-T"
  round 1.8 hole 0.9: 1(0,0) 2(1.27,-2.54) 3(2.54,0) 4(3.81,-2.54) 5(5.08,0) 6(6.35,-2.54) 7(7.62,0) 8(8.89,-2.54) 9(10.16,0) 10(11.43,-2.54)
  round 1.7 hole 1: 11(-1.055,-11.43) 12(-1.055,-13.46) 13(12.495,-11.43) 14(12.495,-13.46)
  round 2.5 hole 1.6: 15(-2.025,-5.84) 16(13.465,-5.84)
  round 1.8 hole 3.25 unplated: 17(0.005,-8.89) 18(11.435,-8.89)
  Top Layer keep-out region: -0.73,1 0.7,1 0.7,1.8 -0.73,1.8
  Top Layer keep-out region: 10.7,1 12.13,1 12.13,1.8 10.7,1.8
  Top Layer keep-out region: -0.595,-8.89 0.635,-8.89 0.635,-4.69 -0.595,-4.69
  Top Layer keep-out region: 10.805,-8.89 12.035,-8.89 12.035,-4.69 10.805,-4.69
  Top Layer keep-out region: 4.135,-16.29 7.335,-16.29 7.335,-15.09 4.135,-15.09
  silkscreen extent -3.8,-19.99 15.2,2.01, body extent -4.19,-19.79 15.64,1.86, height 15.33
SOLDER-BRIDGE_R0603-0R [mil]
  round 10 smd paste-393.7: 1(-19.68,0) 2(23.62,0)
  Top Layer region: -5.91,19.69 13.78,0 -5.91,-19.68 47.24,-19.68 47.24,19.69 -5.91,19.69
  Top Layer region: -47.24,-19.68 -47.24,19.69 -15.75,19.69 3.94,0 -15.75,-19.68 -47.24,-19.68
  silkscreen extent -50,-23 50,23, body extent -36,-20 36,20, height 22
SWI_C&K_SDA02H1SBD_2POS [mm]
  rect 1.5x2.15 smd mask+0.05: 1(-1.27,-4.125) 2(1.27,-4.125) 3(1.27,4.125) 4(-1.27,4.125)
  silkscreen extent -3.55,-3.75 3.55,3.75, body extent -3.53,-4.65 3.53,4.65, height 5.45
SWI_JIUBABA_C-TS-02H-2-5-B-V-T_R_BLUE [mm] "BLUE"
  rect 0.75x1 smd mask+0.05: 1(-2.225,0.75) 2(2.225,0.75) 3(-2.225,-0.75) 4(2.225,-0.75)
  silkscreen extent -1.85,-1.6 1.85,1.6, body extent -2.45,-1.6 2.45,1.6, height 2.6
SWI_JIUBABA_C-TS-02H-2-5-K-V-T_R_BLACK [mm] "BLACK"
  rect 0.75x1 smd mask+0.05: 1(-2.225,0.75) 2(2.225,0.75) 3(-2.225,-0.75) 4(2.225,-0.75)
  silkscreen extent -1.85,-1.6 1.85,1.6, body extent -2.45,-1.6 2.45,1.6, height 2.6
TP [mm] "TP 0402 PAD"
  round 0.6 smd mask+0.09: 1(0,0)
TP_SMD_0-6MM [mm]
  round 0.6 smd paste-10 mask+0.05: 1(0,0)
  silkscreen extent -0.5,-0.5 0.5,0.5
TP_SMD_1MM#1 [mm]
  round 1 smd paste-10 mask+0.05: 1(0,0)
  silkscreen extent -0.7,-0.7 0.7,0.7
TP_SMD_1MM#2 [mm]
  round 1 smd paste-10 mask+0.05: 1(0,0.05)
  silkscreen extent -0.7,-0.7 0.7,0.7

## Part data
B1 B3 B4: library part MCD-00172, "Switch HW SMD blue", Manufacturer=JIUBABA, Manufacturer_Part_Number="C-TS-02H-2.5-B-V-T/R BLUE"
B2: library part MCD-00171, "Switch HW SMD black", Manufacturer=JIUBABA, Manufacturer_Part_Number="C-TS-02H-2.5-K-V-T/R BLACK"
C1 C7 C45 C51 C61 C70 C74 C75 C77 C78 C79 C81 C93 C95 C96 C97 C103 C107 C140 C141 C142 C154 C157 C160 C164 C168 C169 C170 C171 C172 C174 C175 C176 C177 C178 C179 C181 C182 C183 C184 C186 C187 C188: library part MCD-00006, "Capacitor,100nF,16V,X7R,10%,0402", Manufacturer=YAGEO, Manufacturer_Part_Number=CC0402KRX7R7BB104, Package=C0402
C8 C19 C24 C34: library part MCD-00200, "Capacitor, MLCC, 12pF, 50V, NPO, 5%, 0402, T=0,5mm", Manufacturer=YAGEO, Manufacturer_Part_Number=CC0402JRNPO9BN120, Package=C0402
C21 C25 C30 C38 C40 C50 C53 C54 C56 C66 C117 C123 C136 C137: library part MCD-00102, "Capacitor, MLCC, 100nF, 16V, X7R, 10%, 0402, T=0,5mm", Manufacturer=YAGEO, Manufacturer_Part_Number=CC0402KRX7R7BB104, Package=C0402
C23: library part MCD-00009, "Capacitor, MLCC, 4.7uF, 16V, X5R, 10%, 0603, T=0.8mm", Manufacturer=YAGEO, Manufacturer_Part_Number=CC0603KRX5R7BB475, Package=C0603
C28: library part MCD-00012, "Capacitor, MLCC, 2.2uF, 10V, X5R, 10%, 0603, T=0,8mm", Alternate_Manufacturer=KEMET, Alternate_Manufacturer_Part_Number=C0603C225K8PACTU, Manufacturer=YAGEO, Manufacturer_Part_Number=CC0603KRX5R6BB225, Package=C0603
C29: library part MCD-00099, "Capacitor, MLCC, 10uF, 10V, X5R, 10%, 0603, T=0,8mm", Manufacturer=MURATA, Manufacturer_Part_Number=GRM188R61A106KE69D, Package=C0603
C37 C49: library part MCD-01356, "Capacitor, MLCC, 4.7uF, 6V3, X5R, 20%, 0402, T=0,5mm", Manufacturer=MURATA, Manufacturer_Part_Number=GRM155R60J475ME47, Package=C0402
C52: library part MCD-00199, "Polarized Capacitor,10uF,16V,10%,typeA", Manufacturer=AVX, Manufacturer_Part_Number=TAJA106K016R, Package=C1206
C55: library part MCD-00204, "Capacitor, MLCC, 47uF, 10V, X5R, 20%, 0805, T=1,25mm", Manufacturer=MURATA, Manufacturer_Part_Number=GRM21BR61A476ME15K, Package=C0805
C58 C59: library part MCD-00201, "Capacitor, MLCC, 18pF, 50V, NPO, 5%, 0402, T=0,5mm", Manufacturer=YAGEO, Manufacturer_Part_Number=CC0402JRNPO9BN180, Package=C0402
C60: library part MCD-00559, "Capacitor, Tantalum, 47uF, 16V, 10%, TypeC", Manufacturer=AVX, Manufacturer_Part_Number=TAJC476K016RNJ, Package=C2312
C62 C65: library part MCD-00095, "Capacitor, MLCC, 1uF, 6V3, X5R, 10%, 0402, T=0,5mm", Manufacturer=MURATA, Manufacturer_Part_Number=GRM155R60J105KE19, Package=C0402
C69 C167: library part MCD-00205, "Capacitor, MLCC, 100pF, 50V, NPO, 5%, 0402, T=0,5mm", Manufacturer=YAGEO, Manufacturer_Part_Number=CC0402JRNPO9BN101, Package=C0402
C71 C166: library part MCD-00014, "Capacitor, MLCC, 10uF, 25V, X5R, 10%, 0805, T=0,85mm", Manufacturer=YAGEO, Manufacturer_Part_Number=CC0805KRX5R8BB106, Package=C0805
C76 C80 C85 C151 C173 C180: library part MCD-00100, "Capacitor,22uF,6V3,X5R,20%,0603", Manufacturer=MURATA, Manufacturer_Part_Number=GRM188R60J226MEA0J, Package=C0603
C82 C86 C98 C99: library part MCD-00015, "Capacitor,10pF,50V,NPO,5%,0402", Manufacturer=YAGEO, Manufacturer_Part_Number=CC0402JRNPO9BN100, Package=C0402
C83 C84: library part MCD-00724, "Capacitor, MLCC, 470pF, 50V, NPO, 5%, 0402, T=0,5mm", Manufacturer=YAGEO, Manufacturer_Part_Number=CC0402JRNPO9BN471, Package=C0402
C90 C91: "Capacitor, MLCC, 12pF, 50V, NPO, 5%, 0402, T=0,5mm", Manufacturer=YAGEO, Manufacturer_Part_Number=CC0402JRNPO9BN120, Package=C0402
C94 C102 C105 C108 C109 C112: library part MCD-00095, "Capacitor,1uF,6V3,X5R,10%,0402", Manufacturer=MURATA, Manufacturer_Part_Number=GRM155R60J105KE19, Package=C0402
C100 C101: library part MCD-00304, "Capacitor,150pF,50V,COG,5%,0603", Manufacturer=YAGEO, Manufacturer_Part_Number=CC0603JRNPO9BN151, Package=C0603
C104 C110: library part MCD-00010, "Capacitor,1uF,16V,X5R,10%,0603", Manufacturer=YAGEO, Manufacturer_Part_Number=CC0603KRX5R7BB105, Package=C0603
C106 C113: library part MCD-00202, "Capacitor,22nF,16V,X7R,10%,0402", Manufacturer=YAGEO, Manufacturer_Part_Number=CC0402KRX7R7BB223, Package=C0402
C111: library part MCD-00098, "Capacitor,10uF,6V3,X5R,10%,0603", Manufacturer=YAGEO, Manufacturer_Part_Number=CC0603KRX5R5BB106, Package=C0603
C114 C115: library part MCD-00011, "Capacitor, MLCC, 10nF, 16V, X7R, 10%, 0402, T=0.5mm", Manufacturer=YAGEO, Manufacturer_Part_Number=CC0402KRX7R7BB103, Package=C0402
C118 C124 C133 C138: library part MCD-00104, "Capacitor, MLCC, 220uF, 6V3, X5R, 20%, 1206, T=1,6mm", Manufacturer=MURATA, Manufacturer_Part_Number=GRM31CR60J227ME11, Package=C1206
C185 C190: library part MCD-00238, "Capacitor,1uF,6V3,X5R,10%,0603", Manufacturer=YAGEO, Manufacturer_Part_Number=CC0603KRX5R5BB105, Package=C0603
C189: library part MCD-00011, "Capacitor,10nF,16V,X7R,10%,0402", Manufacturer=YAGEO, Manufacturer_Part_Number=CC0402KRX7R7BB103, Package=C0402
CN1 CN5: library part MCD-00109, "USB-Receptacle,Dual-Type-A, RA, TH, Height 15.5mm", Manufacturer=CONEXCON, Manufacturer_Part_Number=5600-3081
CN2: library part MCD-00302, "Header, 20x2, 2.54mm, VR, TH, Height 5.84mm/2.54mm", Manufacturer=SAMTEC, Manufacturer_Part_Number=TSW-120-07-G-D
CN3: library part MCD-00655, "Header 2 circuits, 1.25mm Pitch ,  Vertical, with Friction Lock", Manufacturer=MOLEX, Manufacturer_Part_Number=53047-0210
CN4: "Socket ,TEConn,FCC/FPC, 20pins, 1.0mm,SMT, ZIF Receptacle", Manufacturer="TE CONNECTIVITY", Manufacturer_Part_Number=2-1734248-0
CN6 CN7: library part MCD-01108, "USB tyce C certified receptacle for 1.6mm pcb height", Manufacturer="CHANT SINCERE (COXOC)", Manufacturer_Part_Number=317JD24BZTF3K3C3
CN8: "CONN MAGJACK 1PORT 1000 BASE-T"
CN9: library part MCD-00307, "HDMI Receptacle Type A 19pins standard Connector", Manufacturer=FCI, Manufacturer_Part_Number=10029449-001RLF
CN10: library part MCD-00270, "Connector Jack socket Stereo 3.5mm, 4 pins, RA, SMT, Black", Alternate_Manufacturer=FARNELL, Alternate_Manufacturer_Part_Number=1368640, Manufacturer=LUMBERG, Manufacturer_Part_Number="1503 13 VP3"
CN11: library part MCD-00028, "USB-MICRO-B, 0.65mm, RA, SMT, Bottom Mount,", Manufacturer=MOLEX, Manufacturer_Part_Number=1050170001
CN12: library part MCD-00029, "Header, 4x1, 2,54mm, VR, TH, Height 5.84mm/2.54mm", Manufacturer=SAMTEC, Manufacturer_Part_Number=TSW-104-07-x-S
CN13: library part MCD-00301, "Socket, 10x1, 2.54mm, VR, SMT, Height 9.78mm", Manufacturer=SAMTEC, Manufacturer_Part_Number=SSW-110-22-L-S-VS
CN14 CN16: library part MCD-00300, "Socket, 8x1, 2.54mm, VR, SMT, Height 9.78mm", Manufacturer=SAMTEC, Manufacturer_Part_Number=SSW-108-22-L-S-VS
CN15: "Micro SD SMT bottom conn push-push", Manufacturer=Hirose
CN17: library part MCD-00299, "Socket, 6x1, 2.54mm, VR, SMT, Height 9.78mm", Manufacturer=SAMTEC, Manufacturer_Part_Number=SSW-106-22-L-S-VS
CN95: library part MHDR1x2, "Header, 2-Pin, 50 mil"
D1 D2: library part MCD-00034, "BAT60JFILM", Manufacturer=STMICROELECTRONICS
F1: library part MCD-01133, "Surface mount resettable polyswitch fuse.I hold=0.35A and I trigger=0.75A", Manufacturer="TE CONNECTIVITY", Manufacturer_Part_Number=picoSMDC035S, Package=0805
H1 H2 H3 H4: library part MCD-00035, "POSITION HOLE C6D3R5"
L1: library part MCD-00657, "Inductor,2.4nH,+-0.2nH,0.05R,0.85A,0402", Manufacturer=MURATA, Manufacturer_Part_Number=LQW15AN2N4C00x, Package=L0402
L4: library part MCD-00659, "Inductor, 2.2µH, 20%, Isat 0.35A, DCR 0.2Ohm, 0603", Manufacturer=MURATA, Manufacturer_Part_Number=LQM18PN2R2MGH, Package=L0603
L7: library part MCD-00046, "SMD Chip ferrite bead, 30R@100MHz +/-30%, 5A, 10mohm DC, S (Standard) material, 0603, T=0.8mm", Manufacturer=TDK, Manufacturer_Part_Number=MPZ1608S300A
L8: library part MCD-00305, "Bead,26R at 100Mhz,6A,0603", Manufacturer=MURATA, Manufacturer_Part_Number=BLM18KG260TN1
L10 L11: library part MCD-00094, "Ferrite bead 100R 2A 0603", Manufacturer=MURATA, Manufacturer_Part_Number=BLM18EG101TN1
LD1: library part MCD-00049, "LED, Red, 0603", Manufacturer=EVERLIGHT, Manufacturer_Part_Number=19-213-R6C-AP1Q2B/3T, Package="LED 0603"
LD2 LD3 LD5 LD9: library part MCD-00050, "LED, Green, 0603", Manufacturer=EVERLIGHT, Manufacturer_Part_Number=19-213SYGC/S530-E2/TR8
LD4: library part MCD-00051, "LED Bicolor", Alternate_Manufacturer=EVERLUCK, Alternate_Manufacturer_Part_Number=LE-RGW35280, Manufacturer="AVAGO TECHNOLOGIES", Manufacturer_Part_Number=HSMF-A201-A00J1
LD6: library part MCD-00049, "LED, Red, 0603", Manufacturer=EVERLIGHT, Manufacturer_Part_Number=19-213-R6C-AP1Q2B/3T
LD7: library part MCD-00321, "LED, Orange, 0603", Manufacturer=EVERLIGHT, Manufacturer_Part_Number=19-217/S2C-AM2N2VY/3T, Package="LED 0603"
LD8: library part MCD-01131, "LED Blue, 0603 SMD, Forward Voltage Min=2,8V, Max=3,1V", Manufacturer=EVERLIGHT, Manufacturer_Part_Number=19-217-BHC-ZL1M2RY-3T, Package=0603
LE1: library part MCD-00048, "FIXED IND 4.7UH 1A 180 MOHM 30% SMD", Manufacturer=MURATA, Manufacturer_Part_Number=LQH32PN4R7NN0L
Q1: library part MCD-01120, "Transistor 45V Matched Pair PNP small Signal transistor in SOT363", Manufacturer=DIODES_INC, Manufacturer_Part_Number=BCM857BS7F, Package=SOT363
Q2 T1 T2: library part MCD-01126, "Power Mosfet, P-channel,VDS -30V,RDS 12mohm typ,ID -9A", Manufacturer=STMICROELECTRONICS, Manufacturer_Part_Number=STL9P3LLH6, Package="PowerFLAT 3.3x3.3"
R1 R2 R5 R7 R65 R75 R76 R93 R166 R167: library part MCD-00068, "Resistor,1K5,0402,1%,1/16W", Manufacturer=YAGEO, Manufacturer_Part_Number=RC0402FR-071K5L, Package=R0402
R4 R8 R9 R10 R13 R29 R30 R31 R32 R34 R35 R36 R46 R58 R59 R64 R68 R71 R72 R77 R78 R79 R85 R86 R152 R154 R158 R165: library part MCD-00052, "Resistor,0R,0402,5%,1/16W", Manufacturer=YAGEO, Manufacturer_Part_Number=RC0402JR-070RL, Package=R0402
R11 R18 R19 R40 R42 R80 R81 R84 R87 R96 R99 R109 R164 R300 R600: library part MCD-00053, "Resistor,10K,0402,1%,1/16W", Manufacturer=YAGEO, Manufacturer_Part_Number=RC0402FR-0710KL, Package=R0402
R12 R14 R16 R17 R20 R22 R25 R26 R27 R28 R33 R39 R45 R49 R56 R120: library part MCD-00063, "Resistor,47K,0402,1%,1/16W", Manufacturer=YAGEO, Manufacturer_Part_Number=RC0402FR-0747KL, Package=R0402
R21 R43 R82 R101 R102 R106: library part MCD-00061, "Resistor,1K,0402,1%,1/16W", Manufacturer=YAGEO, Manufacturer_Part_Number=RC0402FR-071KL, Package=R0402
R23 R100 R119 R127 R129 R134 R137 R139 R140 R159 R161: library part MCD-00059, "Resistor,100K,0402,1%,1/16W", Alternate_Manufacturer=YAGEO, Alternate_Manufacturer_Part_Number=RT0402FRE07100KL, Manufacturer_Part_Number=RC0402FR-07100KL, Package=R0402
R24: library part MCD-00187, "Resistor,12K,0402,1%,1/16W", Manufacturer=YAGEO, Manufacturer_Part_Number=RC0402FR-0712KL, Package=R0402
R41 R89 R90 R105: library part MCD-00062, "Resistor,330R,0402,1%,1/16W", Manufacturer=YAGEO, Manufacturer_Part_Number=RC0402FR-07330RL, Package=R0402
R47 R150: library part MCD-00181, "Resistor,0R,0603,ULO", Manufacturer=ROHM, Manufacturer_Part_Number=PMR03EZPJ000, Package=R0603
R48 R57 R70: library part MCD-00333, "Resistor,5K1,0402,1%,1/16W", Manufacturer=YAGEO, Manufacturer_Part_Number=RC0402FR-075K1L, Package=R0402
R50 R51 R52 R53 R54 R55 R67 R91 R94 R149 R156 R163: library part MCD-00065, "Resistor,4K7,0402,1%,1/16W", Alternate_Manufacturer=YAGEO, Alternate_Manufacturer_Part_Number=RT0402FRE074K7L, Manufacturer_Part_Number=RC0402FR-074K7L, Package=R0402
R60 R61 R62 R63 R69 R153: library part MCD-00189, "Resistor,22R,0402,1%,1/16W", Manufacturer=YAGEO, Manufacturer_Part_Number=RC0402FR-0722RL, Package=R0402
R66 R114 R157 R162: library part MCD-00064, "Resistor,510R,0402,1%,1/16W", Manufacturer=YAGEO, Manufacturer_Part_Number=RC0402FR-07510RL, Package=R0402
R83 R151 R160: library part MCD-00056, "Resistor,0R,0603,5%,1/10W", Manufacturer=YAGEO, Manufacturer_Part_Number=RC0603JR-070RL, Package=R0603
R88 R104 R110 R111: library part MCD-00067, "Resistor,100R,0402,1%,1/16W", Manufacturer=YAGEO, Manufacturer_Part_Number=RC0402FR-07100RL, Package=R0402
R92 R103: library part MCD-00485, "Resistor,51R,0402,1%,1/16W", Manufacturer=YAGEO, Manufacturer_Part_Number=RC0402FR-0751RL, Package=R0402
R95 R97 R98: library part MCD-00057, "Resistor,2K2,0402,1%,1/16W", Manufacturer=YAGEO, Manufacturer_Part_Number=RC0402FR-072K2L, Package=R0402
R107 R108: library part MCD-00507, "Resistor,680R,0402,1%,1/16W", Manufacturer=YAGEO, Manufacturer_Part_Number=RC0402FR-07680RL, Package=R0402
R112: library part MCD-00069, "Resistor,36K,0402,1%,1/16W", Manufacturer=YAGEO, Manufacturer_Part_Number=RC0402FR-0736KL, Package=R0402
R155: library part MCD-00183, "Resistor,2K49,0402,1%,1/16W", Manufacturer=YAGEO, Manufacturer_Part_Number=RC0402FR-072K49L, Package=R0402
R201: library part MCD-00185, "Resistor,3K,0402,1%,1/16W", Manufacturer=YAGEO, Manufacturer_Part_Number=RC0402FR-073KL, Package=R0402
SB1 SB2 SB3 SB4 SB5 SB6 SB17 SB19 SB20 SB21 SB22 SB23 SB24 SB25 SB26: library part MCD-00071, "Solder Bridge ON"
SB7 SB8 SB13 SB14 SB15 SB16 SB18: library part MCD-00072, "Solder Bridge OFF"
SW1: library part MCD-00658, "Dip Switch ,2Position ,Surface Mount Slide (Standard) ,2.54 pitch,25mA 24VDC", Manufacturer=C&K, Manufacturer_Part_Number=SDA02H1SBD, Package=DIP
T3 T4: library part MCD-00073, "NPN Bipolar Transistor", Manufacturer=NXP, Manufacturer_Part_Number=BSR14
TP1 TP2 TP3 TP4 TP5 TP6 TP7 TP8 TP9 TP11 TP12 TP15 TP16 TP17 TP18 TP20 TP21 TP23 TP30 TP31 TP32 TP33: library part MCD-00074, "Test Point 1mm", Manufacturer=n/a
TP19 TP53 TP90 TP91 TP93 TP94 TP95 TP96 TP97 TP98 TP99 TP100 TP101 TP102 TP103 TP104 TP400: library part TP, "Testpoint"
TP24 TP25 TP26 TP27 TP28 TP29: library part MCD-00631, "Test Point 0.6mm"
U1 U2 U6 U9 U29: library part MCD-00649, "Common mode filter with ESD protection for USB 2.0 interface", Manufacturer=STMICROELECTRONICS, Manufacturer_Part_Number=ECMF02-2AMX6
U3 U11: library part MCD-00123, "IC,Dual-Channel-Power-Switch,500mA,100mR,SO8", Manufacturer=STMICROELECTRONICS
U7: library part MCD-00145, "USB HUB 2,0 Controller", Manufacturer=MICROCHIP
U8: library part MCD-00268, "IEEE802.11b/g/n W-LAN + Bluetooth 4.1+EDR module", Manufacturer=MURATA
U10 U26: library part MCD-00667, "4-line ESD protection for high speed lines", Manufacturer=STMICROELECTRONICS, Package=uQFN-10L
U12: library part MCD-00676, "USB Type-C controller with VCONN switch", Manufacturer=STMICROELECTRONICS, Manufacturer_Part_Number=STUSB1600QTR
U13: "MPU 18x18 SIP", Manufacturer=Octavo
U14: library part MCD-00267, "HDMI Transmitter, 72-pin 10 × 10 mm QFN", Manufacturer=LATTICE, Manufacturer_Part_Number=SiI9022ACNU
U15 U17: library part MCD-01125, "DUAL TRANSIL ARRAY FOR ESD PROTECTION", Manufacturer=STMICROELECTRONICS, Manufacturer_Part_Number=ESDA25L, Package=ESD_SOT23
U16 U23 U24 U25 U27 U28 U30: library part MCD-01026, "High power transient voltage suppressor", Manufacturer=STMICROELECTRONICS, Manufacturer_Part_Number=ESDA7P120-1U1M, Package=QFN1610
U18: library part MCD-01130, "10/100/1000M GIGABIT Ethernet Transceiver, QFN40 , SMPS version", Manufacturer=REALTEK
U19: library part MCD-00085, "Medium-density performance line ARM-based 32-bit MCU with 128KB Flash", Manufacturer=STMICROELECTRONICS, Manufacturer_Part_Number=STM32F103CBT6
U20: library part MCD-00265, "Low-Power, Stereo Codec with Headphone Amp", Manufacturer="CIRRUS LOGIC", Manufacturer_Part_Number=CS42L51-CNZ
U21: library part MCD-00169, "USB OTG FS ESD protection", Manufacturer=STMICROELECTRONICS, Manufacturer_Part_Number=USBLC6-2P6
U22: library part MCD-00247, "Quad Bidir ESD protection", Manufacturer=STMICROELECTRONICS, Manufacturer_Part_Number=ESDA6V1BC6
U31 U32: library part MCD-00297, "ESD protection & Common Filter High Speed serial Interfaces", Manufacturer=STMICROELECTRONICS, Manufacturer_Part_Number=ECMF04-4HSWM10
U33: library part MCD-01457, "ESD protection , 5 lines", Manufacturer=STMICROELECTRONICS, Package=QFN
U34: library part MCD-00086, "Ultra low drop-low noise BiCMOS voltage, regulators low ESR capacitors compatible", Manufacturer=STMICROELECTRONICS, Manufacturer_Part_Number=LD3985M33R
U35: library part MCD-00170, "ESD protection 6V1", Manufacturer=STMICROELECTRONICS, Manufacturer_Part_Number=ESDALC6V1-1U2
X1: library part MCD-00140, "Crystal, 24.000MHz, 30ppm, 18pF, 7A-24.000MAAE-T", Manufacturer=TXC, Manufacturer_Part_Number=7A-24.000MAAE-T
X2: library part MCD-01463, "Crystal 25Mhz, 10pF, -+50PPM, SMD", Manufacturer=NDK, Manufacturer_Part_Number="NX3225GA 25MHz EXS00A-CG06750", Package=3225
X4: library part MCD-00292, "Surface mount Crystal 32.768kHz, 12.5pF", Manufacturer=NDK, Manufacturer_Part_Number="NX2012SA 32.768kHz EXS00A-MU00528"
X5: library part MCD-00092, "Crystal 8Mhz, 8pF, -+50PPM, SMD", Manufacturer=NDK, Manufacturer_Part_Number="NX3225GD 8MHz EXS00A-CG04874"

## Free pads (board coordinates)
  round 40 smd paste-393.7: FID1(59.06,59.06) FID2(728.35,2519.69) FID3(3917.32,2736.22) FID4(3818.9,39.37)
  round 40 smd far side paste-393.7: FID5(78.74,59.06) FID6(39.37,2755.91) FID7(3897.64,2736.22) FID8(3838.58,39.37)

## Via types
v1: diameter 15.75, hole 7.87, Top Layer to Bottom Layer, tented both sides, 803 vias
v2: diameter 23.62, hole 11.81, Top Layer to Bottom Layer, tented both sides, 417 vias
v3: diameter 15.75, hole 7.87, Top Layer to Bottom Layer, 13 vias

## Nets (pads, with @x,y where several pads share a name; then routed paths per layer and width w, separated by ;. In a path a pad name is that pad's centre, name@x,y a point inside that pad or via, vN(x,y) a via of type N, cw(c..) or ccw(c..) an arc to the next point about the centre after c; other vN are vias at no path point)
1V2_CVCC12: C141.2 C142.2 C164.2 C169.2 C170.2 C172.2 R152.1 U14.5 U14.12 U14.26 U14.42 U14.47 U14.53 | length 1252.4
  Top Layer w11.81: U14.26@2632.87,1101.38 v2(2681.1,1101.38) ; U14.42@2752.95,882.87 v2(2752.95,931.1) ; v2(2772.64,1212.6) U14.12@2772.64,1260.83 ; U14.47@2851.38,882.87 2851.38,915.35 v2(2867.13,931.1) ; v2@2910.43,1213.58 U14.5@2910.43,1260.83 ; U14.53@2969.49,882.87 v2(2969.49,931.1)
  Top Layer w19.68: v2(2909.45,1212.6) v2@2910.43,1213.58
  Signal Layer 4 w19.68: v2(2752.95,931.1) 2781.1,959.25 ; v2(2909.45,1212.6) v2(2772.64,1212.6) 2772.64,1157.87 2753.15,1138.39 2718.11,1138.39 v2(2681.1,1101.38) 2781.1,1001.38 2781.1,959.25 ; v2(2969.49,931.1) 2959.06,941.54 2919.8,941.54 2919.4,941.93 2901.46,941.93 2890.64,931.1 v2(2867.13,931.1) 2867.13,931.86 2839.73,959.25 2781.1,959.25
  Bottom Layer w11.81: C164.2@2650.59,1101.38 v2(2681.1,1101.38) ; C172.2@2752.95,900.59 v2(2752.95,931.1) ; v2(2772.64,1212.6) C142.2@2772.64,1243.11 ; C170.2@2867.13,900.59 v2(2867.13,931.1) ; v2(2909.45,1212.6) 2910.43,1213.58 C141.2@2910.43,1243.11 ; R152.1@2937.01,933.07 2967.52,933.07 v2(2969.49,931.1) C169.2@2969.49,900.59
1V2_HDMI: C160.2 C168.2 R152.2 U13.H4 U14.60 U14.66 | length 1640.4
  Top Layer w11.81: v2(2962.6,1002.95) U14.60@3010.83,1002.95 ; v2(2962.6,1121.06) U14.66@3010.83,1121.06
  Signal Layer 1 w15.75: v1(1968.5,1496.06) 1988.19,1515.75 2384.93,1515.75 2660.52,1240.16 2795.28,1240.16 2914.37,1121.06 v2(2962.6,1121.06)
  Signal Layer 3 w19.68: v2(2962.6,1002.95) v2(2962.6,1121.06)
  Signal Layer 4 w19.68: v2(2962.6,1002.95) v2(2962.6,1121.06)
  Bottom Layer w11.81: R152.2@2937.01,968.5 2937.01,991.14 2948.82,1002.95 v2(2962.6,1002.95) C168.2@2993.11,1002.95 ; v2(2962.6,1121.06) C160.2@2993.11,1121.06
  Bottom Layer w15.75: U13.H4@1948.82,1515.75 v1(1968.5,1496.06)
1V05_AVDD_GMII: C177.2 C178.2 C179.2 C180.2 R160.1 U18.3 U18.8 U18.38 | length 559
  Top Layer w7.87: v2(1018.75,858.32) 1018.75,863.14 1021.65,860.24 1053.15,860.24 U18.38@1057.09,856.3 ; v1(1112.26,768.74) 1112.26,797.08 1114.23,799.05 1114.17,799.1 1114.23,799.16 U18.3@1114.17,799.21 ; v1(1192.91,763.78) U18.8@1192.91,799.21
  Signal Layer 2 w11.81: v2(1018.75,858.32) 1016.73,856.3 1026.57,846.46 1026.57,805.1 1057.07,774.61 1103.46,774.61 1114.17,763.89 1114.23,763.94 1112.26,765.91 v1(1112.26,768.74)
  Bottom Layer w11.81: R160.1@1060.04,671.26 1065.94,671.26 1089.57,694.88 1089.57,705.71 1110.24,726.38 C180.2@1114.17,726.38 ; v1(1112.26,768.74) 1112.26,728.4 1114.23,726.43 C180.2@1114.17,726.38 ; v1(1192.91,763.78) 1193.9,762.8 C178.2@1193.9,729.33 ; C177.2@1229.33,729.33 C178.2@1193.9,729.33 ; C180.2@1114.17,726.38 1117.13,729.33 C179.2@1158.46,729.33 C178.2@1193.9,729.33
